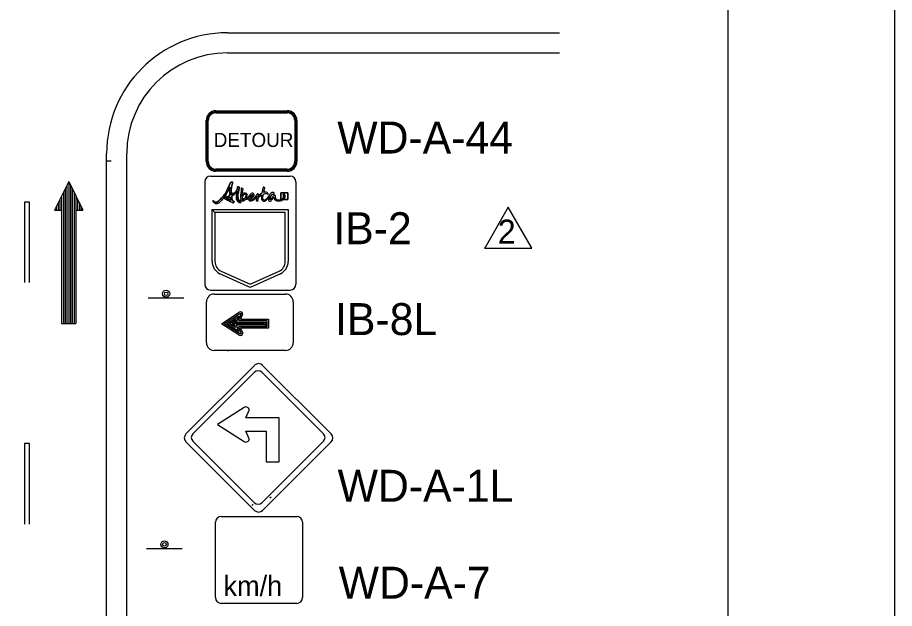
# Model space of a CAD drawing. Extents: x 1806 to 2022, y 110 to 389.
# Drawn here: x 1968.9 to 2021.6, y 244.8 to 280.3 of the extents above; entities that cross this region are included whole.
import ezdxf

# ---------------------------------------------------------------- set-up
doc = ezdxf.new("R2010")
doc.units = 0
for name, color, linetype in [('Level 10', 7, 'Continuous'), ('Level 2', 7, 'Continuous'), ('Level 44', 7, 'Continuous'), ('Level 50', 7, 'Continuous'), ('Level 53', 7, 'Continuous'), ('Level 60', 7, 'Continuous')]:
    doc.layers.add(name, color=color, linetype=linetype)

msp = doc.modelspace()

# ---------------------------------------------------------------- linework, layer by layer
at = {"layer": 'Level 10'}
for p, q in [((1981.525, 279.357), (2001.468, 279.357)), ((1981.525, 278.148), (2001.468, 278.148)), ((1974.267, 233.074), (1974.267, 272.1)), ((1975.477, 233.074), (1975.477, 272.1)), ((1974.285, 271.671), (1974.541, 271.671))]:
    msp.add_line(p, q, dxfattribs=at)
for radius in [7.258, 6.048, 6.048]:
    msp.add_arc((1981.525, 272.1), radius, 90, 180, dxfattribs=at)
at = {"layer": 'Level 2'}
for p, q in [((1980.507, 270.747), (1985.292, 270.747)), ((1980.507, 270.747), (1985.292, 270.747)), ((1980.16, 270.4), (1980.16, 264.245)), ((1985.639, 270.4), (1985.639, 264.245)), ((1969.337, 269.18), (1969.337, 264.342)), ((1969.627, 269.18), (1969.337, 269.18)), ((1969.627, 264.342), (1969.627, 269.18)), ((1980.603, 265.607), (1980.603, 268.734)), ((1980.603, 268.734), (1980.774, 268.563)), ((1980.774, 268.563), (1980.603, 268.734)), ((1980.603, 268.734), (1985.169, 268.734)), ((1985.169, 268.734), (1985.169, 265.607)), ((1980.774, 268.563), (1980.774, 265.607)), ((1984.997, 268.563), (1980.774, 268.563)), ((1984.997, 265.607), (1984.997, 268.563)), ((1981.142, 265.036), (1982.886, 264.242)), ((1982.886, 264.242), (1984.629, 265.036)), ((1982.886, 264.054), (1981.071, 264.88)), ((1984.7, 264.88), (1982.886, 264.054)), ((1980.507, 263.898), (1985.292, 263.898)), ((1969.337, 254.666), (1969.337, 249.828)), ((1969.627, 254.666), (1969.337, 254.666)), ((1969.627, 249.828), (1969.627, 254.666)), ((1984.156, 251.457), (1984.078, 251.379)), ((1983.063, 251.032), (1982.985, 250.954))]:
    msp.add_line(p, q, dxfattribs=at)
for centre, radius, start, end in [((1980.507, 270.4), 0.347, 90, 180), ((1985.292, 270.4), 0.347, 0, 90), ((1981.402, 265.607), 0.799, 180, 245.5432), ((1981.402, 265.607), 0.628, 180, 245.5432), ((1984.37, 265.607), 0.628, 294.4568, 0), ((1984.37, 265.607), 0.799, 294.4568, 0), ((1980.507, 264.245), 0.347, 180, 270), ((1985.292, 264.245), 0.347, 270, 0)]:
    msp.add_arc(centre, radius, start, end, dxfattribs=at)
at = {"layer": 'Level 44'}
for p, q in [((1980.818, 274.543), (1985.109, 274.543)), ((1980.828, 274.664), (1985.119, 274.664)), ((1980.828, 274.599), (1985.119, 274.599)), ((1980.828, 274.545), (1985.119, 274.545)), ((1980.828, 274.545), (1985.119, 274.545)), ((1980.828, 274.545), (1985.119, 274.545)), ((1980.253, 271.624), (1980.253, 274.089)), ((1980.318, 271.624), (1980.318, 274.089)), ((1980.362, 271.622), (1980.362, 274.087)), ((1980.372, 271.624), (1980.372, 274.089)), ((1980.372, 271.624), (1980.372, 274.089)), ((1980.372, 271.624), (1980.372, 274.089)), ((1985.561, 274.087), (1985.561, 271.622)), ((1985.571, 274.089), (1985.571, 271.624)), ((1985.571, 274.089), (1985.571, 271.624)), ((1985.571, 274.089), (1985.571, 271.624)), ((1985.625, 274.089), (1985.625, 271.624)), ((1985.69, 274.089), (1985.69, 271.624)), ((1985.062, 271.265), (1985.066, 271.267)), ((1985.109, 271.159), (1980.818, 271.159)), ((1985.119, 271.161), (1980.828, 271.161)), ((1985.119, 271.161), (1980.828, 271.161)), ((1985.119, 271.161), (1980.828, 271.161)), ((1985.119, 271.107), (1980.828, 271.107)), ((1985.119, 271.042), (1980.828, 271.042)), ((1983.184, 271.153), (1983.184, 271.153)), ((1983.194, 271.155), (1983.194, 271.155)), ((1983.194, 271.155), (1983.194, 271.155)), ((1983.194, 271.155), (1983.194, 271.155)), ((1985.091, 271.207), (1985.095, 271.209)), ((1985.115, 271.159), (1985.119, 271.161)), ((1976.771, 263.433), (1978.904, 263.433)), ((1980.724, 263.652), (1985.015, 263.652)), ((1980.268, 260.73), (1980.268, 263.195)), ((1985.467, 263.195), (1985.467, 260.73)), ((1981.16, 261.875), (1982.235, 262.562)), ((1982.436, 262.451), (1982.308, 262.144)), ((1982.235, 261.192), (1981.16, 261.875)), ((1982.308, 262.144), (1983.985, 262.144)), ((1983.985, 262.144), (1983.985, 261.611)), ((1982.308, 261.611), (1982.44, 261.303)), ((1983.985, 261.611), (1982.312, 261.611)), ((1985.015, 260.265), (1980.724, 260.265)), ((1983.15, 259.371), (1979.029, 255.257)), ((1987.75, 255.257), (1983.636, 259.371)), ((1979.442, 255.254), (1983.15, 258.957)), ((1983.588, 258.957), (1987.291, 255.254)), ((1982.527, 256.838), (1980.919, 255.813)), ((1982.631, 256.213), (1982.832, 256.671)), ((1984.636, 256.213), (1982.631, 256.213)), ((1984.636, 253.578), (1984.636, 256.213)), ((1980.919, 255.813), (1982.524, 254.791)), ((1982.826, 254.959), (1982.628, 255.422)), ((1982.628, 255.422), (1983.845, 255.422)), ((1983.845, 255.422), (1983.845, 253.578)), ((1979.029, 254.769), (1983.15, 250.651)), ((1979.033, 254.769), (1979.029, 254.769)), ((1983.15, 251.109), (1979.442, 254.814)), ((1987.291, 254.814), (1983.588, 251.109)), ((1983.636, 250.651), (1987.75, 254.769)), ((1983.845, 253.578), (1984.636, 253.578)), ((1981.155, 250.288), (1985.683, 250.288)), ((1980.805, 245.409), (1980.805, 249.939)), ((1986.033, 249.939), (1986.033, 245.409)), ((1976.666, 248.369), (1978.799, 248.369)), ((1980.805, 245.408), (1980.805, 245.409)), ((1985.683, 245.06), (1981.155, 245.06))]:
    msp.add_line(p, q, dxfattribs=at)
for points in [[(1983.895, 261.692), (1982.18, 261.692), (1982.35, 261.295), (1982.304, 261.252), (1981.318, 261.875), (1982.308, 262.507), (1982.355, 262.481), (1982.18, 262.059), (1983.899, 262.059), (1983.895, 261.692), (1983.814, 261.781), (1982.052, 261.781), (1982.201, 261.414), (1981.48, 261.875), (1982.201, 262.336), (1982.052, 261.969), (1983.814, 261.969), (1983.814, 261.781), (1983.724, 261.867), (1981.911, 261.867), (1982.009, 261.636), (1981.638, 261.875), (1982.018, 262.118), (1981.962, 261.982), (1981.792, 261.875), (1981.954, 261.768), (1981.92, 261.879), (1981.962, 261.982), (1982.048, 261.922), (1983.72, 261.879), (1983.724, 261.867)], [(1983.895, 261.692), (1982.18, 261.692)], [(1981.518, 260.261), (1981.59, 260.261)]]:
    msp.add_lwpolyline(points, dxfattribs=at)
for centre, radius in [((1977.842, 263.672), 0.213), ((1977.842, 263.672), 0.107), ((1977.737, 248.608), 0.213), ((1977.737, 248.608), 0.107)]:
    msp.add_circle(centre, radius, dxfattribs=at)
for centre, radius, start, end in [((1980.828, 274.09), 0.581, 90, 180), ((1980.828, 274.09), 0.516, 90, 180), ((1980.818, 274.088), 0.462, 90, 180), ((1980.828, 274.09), 0.462, 90, 180), ((1980.828, 274.09), 0.462, 90, 180), ((1980.828, 274.09), 0.462, 90, 180), ((1985.105, 274.088), 0.462, 0, 90), ((1985.115, 274.09), 0.581, 0, 90), ((1985.115, 274.09), 0.516, 0, 90), ((1985.115, 274.09), 0.462, 0, 90), ((1985.115, 274.09), 0.462, 0, 90), ((1985.115, 274.09), 0.462, 0, 90), ((1980.828, 271.621), 0.581, 180, 270), ((1980.828, 271.621), 0.516, 180, 270), ((1980.818, 271.619), 0.462, 180, 270), ((1980.828, 271.621), 0.462, 180, 270), ((1980.828, 271.621), 0.462, 180, 270), ((1980.828, 271.621), 0.462, 180, 270), ((1985.105, 271.619), 0.462, 270, 360), ((1985.115, 271.621), 0.462, 270, 360), ((1985.115, 271.621), 0.462, 270, 360), ((1985.115, 271.621), 0.581, 270, 360), ((1985.115, 271.621), 0.516, 270, 360), ((1985.115, 271.621), 0.462, 270, 360), ((1980.724, 263.196), 0.462, 90, 180), ((1985.011, 263.196), 0.462, 0, 90), ((1982.304, 262.451), 0.132, 0.1051, 122.4986), ((1982.306, 261.302), 0.132, 237.5038, 0.1058), ((1980.724, 260.727), 0.462, 180, 270), ((1985.011, 260.727), 0.462, 270, 0), ((1983.392, 259.129), 0.345, 45, 135), ((1983.368, 258.738), 0.31, 45, 135), ((1982.633, 256.671), 0.198, 359.8942, 122.4962), ((1979.276, 255.013), 0.345, 135, 225), ((1979.663, 255.034), 0.31, 135, 225), ((1982.629, 254.958), 0.198, 237.5014, 359.8949), ((1987.073, 255.034), 0.31, 315, 45), ((1987.509, 255.013), 0.345, 315, 45), ((1983.368, 251.329), 0.31, 225, 315), ((1981.155, 249.937), 0.349, 90, 180), ((1983.392, 250.897), 0.345, 225, 315), ((1985.684, 249.937), 0.349, 360, 90), ((1981.155, 245.408), 0.349, 180, 270), ((1985.684, 245.408), 0.349, 270, 360)]:
    msp.add_arc(centre, radius, start, end, dxfattribs=at)
at = {"layer": 'Level 50'}
for p, q in [((1971.991, 270.415), (1971.138, 268.708)), ((1971.991, 270.415), (1971.991, 261.882)), ((1971.991, 270.415), (1972.845, 268.708)), ((1971.671, 269.775), (1971.671, 261.882)), ((1971.778, 269.988), (1971.778, 261.882)), ((1971.885, 270.202), (1971.885, 261.882)), ((1972.098, 270.202), (1972.098, 261.882)), ((1972.205, 269.988), (1972.205, 261.882)), ((1972.311, 269.775), (1972.311, 261.882)), ((1971.458, 269.348), (1971.458, 268.708)), ((1971.565, 269.562), (1971.565, 261.882)), ((1972.418, 269.562), (1972.418, 261.882)), ((1972.525, 269.348), (1972.525, 268.708)), ((1971.138, 268.708), (1971.565, 268.708)), ((1971.245, 268.922), (1971.245, 268.708)), ((1971.351, 269.135), (1971.351, 268.708)), ((1971.565, 268.708), (1971.565, 261.882)), ((1972.418, 268.708), (1972.418, 261.882)), ((1972.418, 268.708), (1972.845, 268.708)), ((1972.631, 269.135), (1972.631, 268.708)), ((1972.738, 268.922), (1972.738, 268.708)), ((1971.565, 261.882), (1972.418, 261.882))]:
    msp.add_line(p, q, dxfattribs=at)
at = {"layer": 'Level 53'}
msp.add_line((1984.849, 269.33), (1984.748, 269.33), dxfattribs=at)
msp.add_lwpolyline([(1984.849, 269.33), (1985.144, 269.33), (1985.144, 269.737), (1984.736, 269.737), (1984.736, 269.33), (1984.748, 269.33)], dxfattribs=at)
for points, degree in [([(1982.294, 269.182), (1982.251, 269.188), (1982.193, 269.248), (1982.176, 269.346), (1982.145, 269.522), (1982.163, 269.697), (1982.215, 269.956), (1982.225, 270.005), (1982.258, 270.09), (1982.152, 270.107), (1982.118, 270.112), (1982.135, 270.095), (1982.126, 270.05), (1982.085, 269.857), (1981.927, 269.718), (1981.768, 269.624), (1981.752, 269.846), (1981.758, 270.091), (1981.8, 270.242), (1981.835, 270.369), (1981.877, 270.346), (1981.825, 270.373), (1981.771, 270.401), (1981.712, 270.364), (1981.665, 270.269), (1981.617, 270.174), (1981.399, 269.66), (1981.049, 269.313), (1980.871, 269.135), (1980.709, 269.227), (1980.677, 269.254), (1980.651, 269.276), (1980.641, 269.242), (1980.673, 269.207), (1980.818, 269.051), (1981.029, 269.14), (1981.106, 269.217), (1981.318, 269.43), (1981.565, 269.886), (1981.665, 270.08), (1981.656, 269.971), (1981.653, 269.788), (1981.673, 269.573), (1981.565, 269.521), (1981.468, 269.49), (1981.422, 269.478), (1981.373, 269.465), (1981.342, 269.445), (1981.341, 269.422), (1981.34, 269.397), (1981.374, 269.375), (1981.422, 269.353), (1981.507, 269.312), (1981.758, 269.194), (1981.819, 269.158), (1981.872, 269.127), (1981.898, 269.151), (1981.914, 269.184), (1981.934, 269.227), (1981.878, 269.252), (1981.824, 269.268), (1981.803, 269.341), (1981.786, 269.439), (1981.775, 269.547), (1981.902, 269.625), (1982.028, 269.729), (1982.1, 269.86), (1982.082, 269.751), (1982.035, 269.38), (1982.152, 269.223), (1982.178, 269.189), (1982.235, 269.151), (1982.291, 269.157), (1982.317, 269.159), (1982.33, 269.176), (1982.327, 269.182), (1982.325, 269.187), (1982.31, 269.18), (1982.294, 269.182)], 3), ([(1981.768, 269.624), (1981.752, 269.846), (1981.758, 270.091), (1981.8, 270.242), (1981.835, 270.369), (1981.877, 270.346), (1981.825, 270.373), (1981.771, 270.401), (1981.712, 270.364), (1981.665, 270.269), (1981.617, 270.174), (1981.399, 269.66), (1981.049, 269.313), (1980.871, 269.135), (1980.709, 269.227), (1980.677, 269.254), (1980.651, 269.276), (1980.641, 269.242), (1980.673, 269.207), (1980.818, 269.051), (1981.029, 269.14), (1981.106, 269.217), (1981.318, 269.43), (1981.565, 269.886), (1981.665, 270.08)], 3), ([(1981.665, 270.08), (1981.656, 269.971), (1981.653, 269.788), (1981.673, 269.573)], 2), ([(1982.294, 269.182), (1982.251, 269.188), (1982.193, 269.248), (1982.176, 269.346), (1982.145, 269.522), (1982.163, 269.697), (1982.215, 269.956), (1982.225, 270.005), (1982.258, 270.09), (1982.152, 270.107), (1982.118, 270.112), (1982.135, 270.095), (1982.126, 270.05), (1982.085, 269.857), (1981.927, 269.718), (1981.768, 269.624)], 3), ([(1981.775, 269.547), (1981.902, 269.625), (1982.028, 269.729), (1982.1, 269.86)], 2), ([(1982.1, 269.86), (1982.082, 269.751), (1982.035, 269.38), (1982.152, 269.223), (1982.178, 269.189), (1982.235, 269.151), (1982.291, 269.157), (1982.317, 269.159), (1982.33, 269.176), (1982.327, 269.182), (1982.325, 269.187), (1982.31, 269.18), (1982.294, 269.182)], 3), ([(1982.392, 269.518), (1982.401, 269.622), (1982.418, 269.748), (1982.441, 269.866), (1982.451, 269.915), (1982.484, 270), (1982.378, 270.016), (1982.344, 270.022), (1982.349, 270.006), (1982.352, 269.96), (1982.356, 269.899), (1982.288, 269.526), (1982.323, 269.362)], 3), ([(1982.655, 269.397), (1982.731, 269.52), (1982.724, 269.686), (1982.613, 269.714), (1982.485, 269.747), (1982.42, 269.622), (1982.392, 269.518)], 3), ([(1982.879, 269.402), (1982.897, 269.407), (1982.912, 269.412), (1982.926, 269.418), (1983.087, 269.49), (1983.142, 269.598), (1983.101, 269.663), (1983.062, 269.726), (1982.951, 269.707), (1982.863, 269.614), (1982.82, 269.569), (1982.787, 269.49), (1982.783, 269.419)], 3), ([(1983.594, 269.72), (1983.507, 269.67), (1983.426, 269.587), (1983.367, 269.477)], 2), ([(1983.699, 269.763), (1983.711, 269.817), (1983.725, 269.873), (1983.74, 269.926), (1983.753, 269.975), (1983.794, 270.06), (1983.688, 270.077), (1983.655, 270.082), (1983.669, 270.066), (1983.658, 270.02), (1983.638, 269.937), (1983.612, 269.829), (1983.594, 269.72)], 3), ([(1984.622, 269.293), (1984.455, 269.293), (1984.412, 269.423), (1984.404, 269.488), (1984.398, 269.53), (1984.408, 269.592), (1984.334, 269.584), (1984.282, 269.578), (1984.235, 269.478), (1984.17, 269.393), (1984.114, 269.32), (1984.088, 269.327), (1984.101, 269.39), (1984.118, 269.468), (1984.183, 269.651), (1984.258, 269.665), (1984.292, 269.671), (1984.305, 269.61), (1984.321, 269.648), (1984.337, 269.686), (1984.322, 269.768), (1984.245, 269.768), (1984.19, 269.768), (1984.125, 269.711), (1984.072, 269.646), (1984.026, 269.589), (1983.791, 269.243), (1983.693, 269.318), (1983.647, 269.353), (1983.65, 269.495), (1983.679, 269.662)], 3), ([(1983.679, 269.662), (1983.796, 269.707), (1983.893, 269.692), (1983.948, 269.666), (1983.975, 269.653), (1983.979, 269.655), (1983.967, 269.685), (1983.95, 269.728), (1983.856, 269.797), (1983.71, 269.765), (1983.706, 269.765), (1983.703, 269.764), (1983.699, 269.763)], 3), ([(1984.736, 269.737), (1984.736, 269.737), (1984.736, 269.33), (1984.736, 269.33), (1984.736, 269.33), (1984.748, 269.33), (1984.748, 269.33), (1984.837, 269.383), (1984.896, 269.484), (1984.896, 269.567), (1984.896, 269.639), (1984.858, 269.635), (1984.862, 269.645), (1984.874, 269.674), (1984.964, 269.658), (1984.97, 269.556), (1984.974, 269.47), (1984.929, 269.387), (1984.849, 269.33), (1984.849, 269.33), (1985.144, 269.33), (1985.144, 269.33), (1985.144, 269.33), (1985.144, 269.737), (1985.144, 269.737), (1985.144, 269.737), (1984.736, 269.737), (1984.736, 269.737)], 3), ([(1981.673, 269.573), (1981.565, 269.521), (1981.468, 269.49), (1981.422, 269.478), (1981.373, 269.465), (1981.342, 269.445), (1981.341, 269.422), (1981.34, 269.397), (1981.374, 269.375), (1981.422, 269.353), (1981.507, 269.312), (1981.758, 269.194), (1981.819, 269.158), (1981.872, 269.127), (1981.898, 269.151), (1981.914, 269.184), (1981.934, 269.227), (1981.878, 269.252), (1981.824, 269.268)], 3), ([(1981.478, 269.403), (1981.534, 269.424), (1981.606, 269.454), (1981.682, 269.493)], 2), ([(1981.478, 269.403), (1981.534, 269.424), (1981.606, 269.454), (1981.682, 269.493), (1981.692, 269.407), (1981.703, 269.344), (1981.715, 269.298), (1981.66, 269.318), (1981.581, 269.351), (1981.478, 269.403)], 3), ([(1981.715, 269.298), (1981.66, 269.318), (1981.581, 269.351), (1981.478, 269.403)], 2), ([(1981.682, 269.493), (1981.692, 269.407), (1981.703, 269.344), (1981.715, 269.298)], 2), ([(1981.824, 269.268), (1981.803, 269.341), (1981.786, 269.439), (1981.775, 269.547)], 2), ([(1982.323, 269.362), (1982.277, 269.348), (1982.259, 269.313), (1982.318, 269.277), (1982.358, 269.252), (1982.448, 269.243), (1982.538, 269.288), (1982.571, 269.304), (1982.599, 269.326), (1982.622, 269.353)], 3), ([(1982.406, 269.295), (1982.412, 269.3), (1982.416, 269.307), (1982.416, 269.316), (1982.416, 269.321), (1982.416, 269.327), (1982.416, 269.333)], 3), ([(1982.443, 269.295), (1982.428, 269.293), (1982.416, 269.293), (1982.406, 269.295)], 2), ([(1982.416, 269.333), (1982.439, 269.334), (1982.475, 269.337), (1982.518, 269.341)], 2), ([(1982.42, 269.374), (1982.437, 269.504), (1982.505, 269.686), (1982.59, 269.657), (1982.639, 269.64), (1982.613, 269.487), (1982.55, 269.385)], 3), ([(1982.55, 269.385), (1982.509, 269.381), (1982.466, 269.377), (1982.42, 269.374)], 2), ([(1982.518, 269.341), (1982.495, 269.316), (1982.47, 269.299), (1982.443, 269.295)], 2), ([(1982.622, 269.353), (1982.676, 269.36), (1982.733, 269.368), (1982.784, 269.379)], 2), ([(1982.783, 269.419), (1982.746, 269.411), (1982.703, 269.404), (1982.655, 269.397)], 2), ([(1982.784, 269.379), (1982.793, 269.307), (1982.84, 269.252), (1982.948, 269.262), (1983.103, 269.276), (1983.24, 269.466), (1983.292, 269.558)], 3), ([(1983.367, 269.477), (1983.378, 269.528), (1983.394, 269.584), (1983.395, 269.621), (1983.396, 269.661), (1983.369, 269.67), (1983.358, 269.673), (1983.335, 269.679), (1983.307, 269.668), (1983.279, 269.629), (1983.215, 269.538), (1983.133, 269.394), (1983.009, 269.334), (1982.92, 269.291), (1982.881, 269.334), (1982.879, 269.402)], 3), ([(1982.965, 269.606), (1983.019, 269.656), (1983.046, 269.653), (1983.053, 269.639), (1983.069, 269.61), (1983.005, 269.507), (1982.883, 269.451)], 3), ([(1982.883, 269.451), (1982.894, 269.506), (1982.923, 269.566), (1982.965, 269.606)], 2), ([(1983.292, 269.558), (1983.283, 269.46), (1983.219, 269.246), (1983.328, 269.257), (1983.37, 269.261), (1983.352, 269.268), (1983.355, 269.304), (1983.364, 269.434), (1983.471, 269.543), (1983.578, 269.61)], 3), ([(1983.578, 269.61), (1983.559, 269.452), (1983.566, 269.311), (1983.637, 269.266), (1983.769, 269.184), (1983.956, 269.401), (1984.059, 269.533)], 3), ([(1984.059, 269.533), (1984.006, 269.415), (1983.977, 269.264), (1984.055, 269.241), (1984.147, 269.214), (1984.22, 269.367), (1984.305, 269.484)], 3), ([(1984.305, 269.484), (1984.315, 269.4), (1984.371, 269.256), (1984.597, 269.256), (1984.698, 269.256), (1984.785, 269.284), (1984.849, 269.33)], 3), ([(1984.748, 269.33), (1984.711, 269.307), (1984.668, 269.293), (1984.622, 269.293)], 2), ([(1984.748, 269.33), (1984.837, 269.383), (1984.896, 269.484), (1984.896, 269.567), (1984.896, 269.639), (1984.858, 269.635), (1984.862, 269.645), (1984.874, 269.674), (1984.964, 269.658), (1984.97, 269.556), (1984.974, 269.47), (1984.929, 269.387), (1984.849, 269.33)], 3)]:
    msp.add_open_spline(points, degree=degree, dxfattribs=at)
at = {"layer": 'Level 60'}
for points in [[(1805.588, 389.179), (2021.588, 389.179), (2021.588, 110.179), (1805.588, 110.179)], [(1824.714, 378.37), (2011.588, 378.37), (2011.588, 120.988), (1824.714, 120.988)]]:
    msp.add_lwpolyline(points, close=True, dxfattribs=at)
for points in [[(1998.388, 268.883), (1996.995, 266.458)], [(1999.782, 266.458), (1998.388, 268.883)], [(1996.995, 266.458), (1996.969, 266.413), (1999.808, 266.413), (1999.782, 266.458)]]:
    msp.add_lwpolyline(points, dxfattribs=at)

# ---------------------------------------------------------------- texts
at = {"layer": 'Level 44'}
msp.add_text('DETOUR', height=0.8479, rotation=360, dxfattribs=at).set_placement((1980.699, 272.495))
msp.add_text('km/h', height=1.218, dxfattribs=at).set_placement((1981.285, 245.502))
msp.add_text('km/h', height=1.218, dxfattribs=at).set_placement((1981.285, 245.502))
at = {"layer": 'Level 50'}
for s, p in [('WD-A-44', (1988.12, 272.103)), ('IB-2', (1987.884, 266.652)), ('IB-8L', (1987.988, 261.19)), ('WD-A-1L', (1988.142, 251.171)), ('WD-A-7', (1988.204, 245.348))]:
    msp.add_text(s, height=1.9199, rotation=360, dxfattribs=at).set_placement(p)
at = {"layer": 'Level 60'}
msp.add_text('2', height=1.448, rotation=360, dxfattribs=at).set_placement((1997.761, 266.682))

doc.saveas('drawing.dxf')
